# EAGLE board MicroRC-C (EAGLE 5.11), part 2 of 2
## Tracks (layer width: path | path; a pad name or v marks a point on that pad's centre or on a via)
+2V5  (via drill 0.41)
  Top 0.254: U10.1 U10.2 121.28,5.4 120.97,5.71 v120.97,6.67 | R46.2 R62.2 R16.2 v111.44,13.65
  Bottom 0.254: v120.97,6.67 118.11,6.67 117.79,6.98 117.79,8.89 117.47,9.21 112.08,9.21 111.44,9.84 v111.44,13.65
+3V3  (via drill 0.41, 0.61)
  Top 0.254: 108.58,51.59 TP2.TP
  Top 0.406: 121.21,46.6 120.97,46.6 v120.97,45.08
  Top 0.61: 121.21,46.6 U4.1 | v108.58,49.85 108.58,51.59
  Top 0.813: C21.+
  Top 1.016: v108.58,49.85 C21.+ v113.35,49.85
  SUPPLY 0.61: v120.97,45.08 120.97,49.21 120.33,49.85 v113.35,49.85 112.39,49.85 111.76,49.21 111.76,30.64 112.71,29.69 v117.47,29.69 | v108.58,49.85 108.58,46.67 109.54,45.72 109.54,34.61 107.63,32.7 v107.63,30.8
  pour Top (isolate 0.406, no thermals): 115.57,30.16 116.2,30.8 117.47,30.8 118.43,31.75 118.43,34.61 119.06,34.61 119.06,32.07 119.38,31.75 120.65,31.75 120.97,31.43 120.97,29.21 115.57,29.21
  pour Top (isolate 0.305, no thermals): 107,34.61 107.63,34.61 107.63,32.07 107.95,31.75 109.22,31.75 109.54,31.43 109.54,29.21 104.14,29.21 104.14,30.96 106.68,30.96 107,31.27
+5V  (via drill 0.41, 0.61)
  Top 0.178: R69.2 111.6,27.62 111.44,27.78 R70.2 110.49,27.62 110.33,27.78 v110.33,30.8 | R18.2 v62.23,44.77 | C11.1 v32.7,13.97 | U3.22 v28.26,11.11
  Top 0.254: R11.2 | R11.2 | R11.2 v50.48,51.12 | R10.2 v50.48,53.02 | C74.+ 81.92,30.16 v81.92,32.07 81.92,33.34 81.6,33.65 80.64,33.65 U6.18 | v77.47,26.35 C73.1 C30.2 TP1.TP | R20.2 v61.28,11.11 | C9.1 v46.04,54.93 U1.8 | R74.2 v133.67,4.13 | R79.2 40.64,40.96 40.01,41.59 v39.05,41.59 | U3.26 27.87,13.72 28.26,13.33 v28.26,11.11 | RN1.5 RN1.6 RN1.7 RN1.8 v43.02,11.43 | U8.24 98.51,34.68 99.06,34.13 v99.06,31.27 C72.1
  Top 0.406: R50.1 v66.04,32.38 | v28.26,11.11 C22.1
  Top 0.61: v20.8,33.65 R7.1
  Top 0.813: R6.1 v39.05,41.59
  Top 1.27: L3.2 v71.44,16.83
  other vias: 87.63,57.47 89.53,59.05 87.63,59.05 89.53,57.47
  pour SUPPLY (isolate 0.305, rank 2, no thermals): 0.95,75.88 0.95,52.7 5.71,52.7 6.03,52.39 6.03,49.85 5.71,49.53 0.95,49.53 0.95,0.95 133.99,0.95 133.99,4.13 arc90 133.67,4.44 arc90 133.35,4.13 133.35,2.86 arc-90 132.08,1.59 76.2,1.59 arc-90 74.93,2.86 74.93,23.81 arc-90 76.2,25.08 102.87,25.08 arc90 103.5,25.72 103.5,26.99 arc-90 104.78,28.26 121.92,28.26 arc90 122.56,28.89 122.56,33.02 arc-90 123.83,34.29 124.78,34.29 arc90 125.41,34.92 arc90 124.78,35.56 123.83,35.56 arc-90 122.56,36.83 122.56,71.12 arc90 121.92,71.75 53.34,71.75 arc90 52.7,71.12 52.7,59.69 arc-90 51.44,58.42 48.26,58.42 arc-90 46.99,59.69 46.99,75.88
  pour Top (isolate 0.61, rank 2, no thermals): 66.67,65.09 66.67,61.59 67.94,60.32 95.25,60.32 95.25,56.51 75.56,56.51 75.56,57.78 68.26,57.78 68.26,56.83 62.87,56.83 62.87,65.09
+12V  (via drill 0.41, 0.61)
  Top 0.254: v111.44,7.3 R73.2 | 119.38,23.81 v118.11,23.81 U7.8 | 119.38,23.81 | 119.38,23.81 C77.1
  Top 0.406: v120.97,7.94 U10.4 124.46,7.94 125.09,7.3 C75.1 | v95.57,13.65 C76.1 93.98,13.65 93.98,12.38 93.03,11.43 93.03,8.57 93.66,7.94 U5.4 | U4.3 121.28,49.6 121.28,51.75 121.76,52.23 v123.83,52.23
  other vias: 50.01,63.18 50.01,61.59 50.01,60.01
  pour Top (isolate 0.61, rank 5, no thermals): 27.3,61.59 27.3,57.78 59.05,57.78 59.69,57.15 59.69,54.61 60.96,54.61 60.96,67.94 61.59,68.58 66.36,68.58 66.36,69.85 60.01,69.85 58.74,68.58 58.74,64.77 58.1,64.13 41.91,64.13 41.27,64.77 41.27,69.85 40.32,70.8 36.2,70.8 36.2,69.85 39.05,69.85 39.37,69.53 39.37,62.23 38.73,61.59
  pour SUPPLY (isolate 0.305, rank 3, no thermals): 47.62,75.88 47.62,59.69 arc90 48.26,59.05 51.44,59.05 arc90 52.07,59.69 52.07,71.12 arc-90 53.34,72.39 121.92,72.39 arc-90 123.19,71.12 123.19,36.83 arc90 123.83,36.19 124.78,36.19 arc-90 126.05,34.92 arc-90 124.78,33.65 123.83,33.65 arc90 123.19,33.02 123.19,28.89 arc-90 121.92,27.62 104.78,27.62 arc90 104.14,26.99 104.14,25.72 arc-90 102.87,24.45 76.2,24.45 arc90 75.56,23.81 75.56,2.86 arc90 76.2,2.22 132.08,2.22 arc90 132.72,2.86 132.72,4.13 arc-90 133.67,5.08 arc-90 134.62,4.13 134.62,0.95 153.35,0.95 153.35,75.88
AGND  (via drill 0.41, 0.61)
  Top 0.178: 37.31,22.07 U12.2 | v34.61,26.99
  Top 0.254: C57.2 v84.14,27.62 | R77.1 v111.44,4.13 C65.2 | U7.4 v109.22,20 | C66.2 v138.11,4.13 | R78.1 v124.78,4.13 | C77.2 v122.87,23.49 | C76.2 92.71,13.33 | U5.11 92.39,7.94 92.87,7.46 v92.87,6.67 | C8.2 v34.61,26.99 | R33.1 v107,16.83 | R38.2 v79.69,10.48 | C38.1 v88.58,7.3 | R39.2 v84.14,10.48 | R40.2 v79.69,4.13 | D10.A v87.63,20.48 87.63,16.83 R37.2 | C19.2 v70.8,11.11 | C19.2 C19.2 arc-270 C19.2 | C19.2 68.9,13.65 R22.1 | R66.1 140.52,25.53 141.29,24.76 141.29,23.49 141.6,23.18 C60.2 R67.2 | C78.- v80.64,20.48 | R71.1 149.19,4.13 C62.2
  Top 0.406: C56.- v83.82,51.43 | U9.23 v113.67,31.75 | C63.1 v102.23,26.35 | v115.89,7.94 U10.11 | v91.12,13.65 C76.2 | C75.2 v129.22,7.3 | C55.- v87.63,51.43 | R23.1 C20.2 v61.91,54.93 | D7.A v58.42,55.88
  Top 0.61: C4.1 v34.61,24.92 34.61,22.54 | v42.86,56.83 52.39,56.83 53.34,55.88 D7.A | 34.61,22.54 C79.- | 37.31,22.07 34.61,22.07 34.61,22.54 | C79.- 34.61,22.54 | C79.-
  Bottom 0.406: v61.91,54.93 60.96,54.93 60.01,55.88 v58.42,55.88
  other vias: 106.68,44.77 117.47,26.67 140.97,49.85 140.97,37.46 134.94,28.57 128.27,20.32 129.86,31.11 152.4,31.75 152.4,2.54 99.38,69.21 99.38,67.94 70.8,6.67 70.8,2.22 109.22,25.72
  pour GROUND (isolate 0.305, rank 3, no thermals): 81.28,60.64 81.28,48.26 arc90 81.92,47.62 104.14,47.62 arc-90 105.41,46.35 105.41,44.45 arc90 106.05,43.81 112.08,43.81 arc90 112.71,44.45 112.71,46.51 arc-90 113.98,47.78 121.6,47.78 arc-90 122.87,46.51 122.87,34.29 arc90 123.51,33.65 124.78,33.65 arc-90 126.05,32.38 126.05,32.38 arc-90 124.78,31.11 123.51,31.11 arc90 122.87,30.48 122.87,28.89 arc-90 121.6,27.62 115.57,27.62 arc-90 114.3,28.89 114.3,31.59 arc90 113.67,32.23 arc90 113.03,31.59 113.03,28.1 arc-90 111.76,26.83 102.23,26.83 arc90 101.6,26.19 101.6,25.72 arc-90 100.33,24.45 86.04,24.45 arc-90 84.77,25.72 84.77,27.62 arc180 83.5,27.62 83.5,25.72 arc-90 82.23,24.45 76.36,24.45 arc90 75.72,23.81 75.72,13.02 arc-90 74.45,11.75 70.48,11.75 arc90 69.85,11.11 69.85,0.95 153.35,0.95 153.35,75.88 93.03,75.88 93.03,62.55 arc-90 91.76,61.28 81.92,61.28 arc90 81.28,60.64
  pour Top (isolate 0.61, rank 3, no thermals): 121.28,50.8 121.28,38.42 122.56,37.15 122.56,18.1 138.11,18.1 138.11,28.42 142.24,28.42 142.24,50.8 141.6,51.43 140.34,51.43 139.7,52.07 139.7,59.69 140.34,60.32 144.15,60.32 147,57.47 147,49.21 152.08,49.21 152.72,48.58 152.72,32.7 151.76,32.07 151.76,31.43 152.72,30.48 152.72,4.13 150.81,2.22 74.93,2.22 73.98,3.17 73.98,13.97 72.71,13.97 72.39,14.29 72.39,15.24 70.17,15.24 70.17,1.59 153.35,1.59 153.35,75.25 144.3,75.25 144.3,61.91 143.99,61.59 133.67,61.59 133.35,61.28 133.35,50.8
  pour Bottom (isolate 0.61, rank 2, no thermals): 34.92,75.25 34.92,28.26 33.97,27.3 33.97,23.34 34.29,23.02 38.42,23.02 38.42,35.24 42.23,35.24 42.23,54.61 44.77,57.15 49.53,57.15 58.42,66.04 116.84,66.04 120.65,62.23 120.65,51.12 128.27,51.12 128.27,36.19 127.95,35.88 126.68,35.88 126.36,35.56 126.36,34.29 126.68,33.97 127.95,33.97 128.27,33.65 128.27,28.26 126.36,28.26 126.36,25.08 123.19,25.08 122.24,24.13 122.24,19.37 129.54,19.37 130.49,18.41 136.21,18.41 136.21,16.19 142.88,16.19 142.88,8.25 139.06,8.25 139.06,7.3 129.86,7.3 129.54,7.62 128.91,7.62 128.59,7.3 122.56,7.3 120.02,4.76 110.49,4.76 109.54,5.71 105.41,5.71 102.87,3.17 80.96,3.17 78.11,6.03 78.11,8.57 70.17,8.57 70.17,1.59 153.35,1.59 153.35,75.25
  pour Top (isolate 0.61, no thermals): 104.78,47.31 107.31,47.31 107.63,46.99 107.63,42.23 105.73,42.23 105.73,44.77 105.41,45.08 105.09,45.08 104.78,45.4
  pour Top (isolate 0.406, rank 2, no thermals): 115.25,27.94 120.97,27.94 120.97,25.72 113.35,25.72 112.71,25.08 107,25.08 107,25.4 107.95,26.35 114.94,26.35 115.25,26.67
  pour Top (no thermals): 97.47,69.21 98.11,69.85 100.01,69.85 100.01,67.31 98.11,67.31 97.47,67.94
AUX_AUDIO  (via drill 0.41)
  Top 0.254: X3.8 142.88,53.34 142.88,43.81 | v142.88,21.59 v142.88,36.19 142.88,43.81 | C45.2 v124.78,13.65 | 142.88,43.81 R49.2
  Bottom 0.254: v142.88,21.59 142.88,15.87 142.24,15.24 127.32,15.24 125.73,13.65 v124.78,13.65 | J2.3 130.81,29.84 137.16,36.19 v142.88,36.19
  Bottom 0.61: X3.8 X4.8
AUX_AUDIO_OUT  (via drill 0.41)
  Top 0.254: U7.1 v109.22,23.81 TP4.TP | U8.22 94.35,33.28 94.93,32.7 v94.93,31.75
  Bottom 0.254: v94.93,31.75 94.93,24.76 95.89,23.81 v109.22,23.81
AVR_5V  (via drill 0.41, 0.61)
  Top 0.178: D1.C C1.1 | U2.52 40.11,31.22 39.85,30.96 C2.1
  Top 0.254: R5.2 C1.1 60.96,18.41 60.64,18.73 60.64,20.95 | 57.01,24.84 U2.21 | U2.52 42.34,31.22 v43.02,31.91
  Top 0.406: R5.2 59.05,16.83 | v55.56,24.84 57.01,24.84
  Top 0.813: L2.2 60.64,20.95 v60.64,22.7
  SUPPLY 0.406: v60.64,22.7 56.2,22.7 55.56,23.34 v55.56,24.84 53.42,24.84 46.35,31.91 v43.02,31.91
AVR_REF
  Top 0.178: 39.21,21.75 U12.1
  Top 0.254: C4.2 37.78,23.49 38.1,23.18 38.89,23.18 39.21,22.86 39.21,21.75 | U2.64 41.41,21.75 39.21,21.75 | 39.21,21.75 | 39.21,21.75 U12.1
B_CTS
  Top 0.178: U3.6 19.34,11.77 19.05,12.06 7.62,12.06 6.67,13.02 6.67,17.46 6.87,17.67 X2.8
B_DCD
  Top 0.178: X2.1 12.72,24.59 13.49,23.81 13.49,20.32 13.81,20 21.59,20 22.86,18.73 22.86,11.27 22.06,10.47 U3.8
B_DSR
  Top 0.178: X2.6 12.36,23.2 13.02,22.54 13.02,20.16 13.65,19.53 21.43,19.53 22.38,18.57 22.38,11.75 21.76,11.12 U3.7
B_DTR  (via drill 0.41)
  Top 0.178: U3.10 18.29,9.17 18.1,9.37 v18.1,10.64
  Bottom 0.178: X2.4 17.53,16.28 18.1,15.72 v18.1,10.64
B_RI
  Top 0.178: U3.4 19.58,13.07 19.05,12.54 12.7,12.54 12.38,12.86 12.38,14.6 12.09,14.9 X2.9
B_RTS
  Top 0.178: X2.7 6.46,20.43 5.71,19.68 5.71,12.7 7.3,11.11 16.83,11.11 17.14,10.79 17.14,8.89 17.52,8.52 U3.11
B_RXD
  Top 0.178: X2.2 12.15,21.82 12.54,21.43 12.54,20 13.49,19.05 21.27,19.05 21.91,18.41 21.91,12.7 21.63,12.42 U3.5
B_TXD
  Top 0.178: X2.3 6.67,19.05 6.19,18.57 6.19,12.86 7.46,11.59 18.73,11.59 19.05,11.27 19.05,10.16 19.39,9.82 U3.9
BEEP_PWM  (via drill 0.41)
  Top 0.178: R68.1 v73.66,16.83 TP7.TP | U2.15 54.41,18.93 55.24,18.1 v55.24,17.3
  Bottom 0.178: v55.24,17.3 66.99,17.3 68.26,18.57 73.34,18.57 73.66,18.26 v73.66,16.83
CGND  (via drill 0.61)
  Top 0.178: R13.2 111.12,53.97 110.81,54.29
  Bottom 0.61: X3.4 X4.4
  other vias: 94.3,69.21 94.3,67.94
  pour Top (isolate 0.61, rank 6, no thermals): 12.7,75.25 12.7,70.48 15.56,70.48 15.88,70.17 15.88,64.77 17.14,64.77 17.78,65.41 17.78,72.39 18.41,73.02 30.8,73.02 31.43,72.39 31.43,69.85 33.66,69.85 33.97,69.53 33.97,66.04 34.29,65.72 35.56,65.72 35.88,65.41 35.88,62.86 37.78,62.86 37.78,68.58 37.47,68.9 35.88,68.9 35.56,69.21 35.56,71.75 35.88,72.07 40.96,72.07 42.23,70.8 58.74,70.8 59.37,71.44 69.22,71.44 69.85,70.8 69.85,61.91 70.48,61.28 95.89,61.28 96.52,60.64 96.52,56.51 110.17,56.51 110.17,53.66 111.44,53.66 111.44,56.51 122.56,56.51 122.56,53.66 124.14,53.66 124.78,53.02 124.78,51.43 132.08,51.43 132.08,61.91 133.03,62.86 143.19,62.86 143.19,64.13 129.86,64.13 126.36,60.64 101.92,60.64 101.92,75.25
COM_CTS  (via drill 0.41)
  Top 0.178: U3.17 24.2,7.87 v23.5,8.57 | U2.14 53.61,17.89 53.34,17.62 v52.55,17.62
  Bottom 0.178: v23.5,8.57 23.5,15.87 23.97,16.35 47.15,16.35 49.05,18.26 50.64,18.26 51.28,17.62 v52.55,17.62
COM_DCD  (via drill 0.41)
  Top 0.178: U2.8 48.81,18.18 v49.53,17.46 | v27.78,9.37 27.78,6.98 27.37,6.57 U3.15
  Bottom 0.178: v49.53,17.46 49.53,16.51 50.16,15.87 50.16,14.29 49.85,13.97 47.62,13.97 46.67,14.92 27.3,14.92 26.99,14.6 26.99,10.95 27.78,10.16 v27.78,9.37
COM_DSR  (via drill 0.41)
  Top 0.178: U3.16 23.74,7.22 23.02,7.94 v22.23,7.94 | U2.17 56.67,21.62 56.67,19.21 56.04,18.57 56.04,16.51 55.72,16.19 v53.02,16.19
  Bottom 0.178: v53.02,16.19 53.5,16.67 53.5,18.57 53.18,18.89 48.74,18.89 46.83,16.99 22.86,16.99 22.23,16.35 v22.23,7.94
COM_DTR  (via drill 0.41)
  Top 0.178: U2.35 53.61,40.91 v55.24,42.54 | v61.28,33.97 62.23,33.97 62.87,34.61 67.63,34.61 68.42,33.81 v69.22,33.81 | 20.64,7.22 22.94,7.22 23.65,6.51 v23.65,5.71 | U3.12 20.64,7.87 20.64,7.22 | 20.64,7.22 U3.13
  Bottom 0.178: v69.22,33.81 69.22,36.19 69.85,36.83 82.55,36.83 83.19,36.19 83.19,25.72 82.55,25.08 78.11,25.08 77.47,24.45 77.47,10.48 76.83,9.84 59.37,9.84 56.83,12.38 30,12.38 29.69,12.06 29.69,9.05 26.35,5.71 v23.65,5.71 | v55.24,42.54 57.63,42.54 58.42,41.75 60.64,41.75 61.28,41.12 61.28,34.13 v61.28,33.97
COM_RXD  (via drill 0.41)
  Top 0.178: R3.2 v49.21,14.92 49.21,15.56 48.9,15.87 44.77,15.87 44.01,16.63 U2.2 | v24.77,8.89 25.4,8.89 25.77,8.52 U3.18
  Bottom 0.178: v49.21,14.92 47.94,14.92 47.15,15.72 26.35,15.72 26.04,15.4 26.04,9.21 25.72,8.89 v24.77,8.89
COM_TXD  (via drill 0.41)
  Top 0.178: R1.2 51.75,14.6 50.8,15.56 v50.8,16.51 45.24,16.51 44.81,16.94 U2.3 | U3.14 22,6.57 22.23,6.35 v22.23,5.71
  Bottom 0.178: v50.8,16.51 50.8,13.81 50.01,13.02 29.69,13.02 29.05,12.38 29.05,9.21 26.83,6.98 22.54,6.98 22.23,6.67 v22.23,5.71
COS  (via drill 0.41)
  Top 0.178: v120.97,55.56 120.97,53.66 119.38,52.07 R13.1 v110.81,52.07 | R19.2 v66.67,51.43
  Bottom 0.178: v120.97,55.56 120.97,65.41 121.6,66.04 X3.3 | v110.81,52.07 102.87,52.07 100.97,53.97 66.99,53.97 66.67,53.66 v66.67,51.43
  Bottom 0.61: X3.3 X4.3
CS_DTMF  (via drill 0.41)
  Top 0.178: U2.38 51.21,34.38 50.8,33.97 48.26,33.97 47.62,33.34 v47.62,23.97 | v70.48,31.75 U6.10
  Bottom 0.178: v47.62,23.97 52.39,23.97 56.67,19.68 61.91,19.68 63.66,21.43 67.15,21.43 68.58,22.86 68.58,28.26 70.48,30.16 v70.48,31.75
DISC_AUDIO
  Top 0.254: X3.6 144.46,58.42 146.05,56.83 146.05,49.21 146.72,48.54 R26.3 151.81,48.54 152.08,48.26 152.08,33.65 151.72,33.3 R27.3
  Bottom 0.61: X3.6 X4.6
DTMF_Q1
  Top 0.178: 61.12,35.08 59.85,33.81 59.85,31.75 59.32,31.22 U2.29 | 61.12,35.08 | 61.12,35.08 71.6,35.08 71.75,34.92 U6.11
DTMF_Q2
  Top 0.178: U6.12 73.03,34.92 72.39,35.56 60.96,35.56 59.37,33.97 59.37,32.54 58.85,32.02 U2.30
DTMF_Q3
  Top 0.178: U6.13 74.3,34.92 73.18,36.04 60.8,36.04 58.9,34.13 58.9,33.34 58.38,32.82 U2.31
DTMF_Q4
  Top 0.178: U6.14 75.56,34.92 73.98,36.51 60.64,36.51 58.42,34.29 58.42,33.97 58.07,33.62 U2.32
EXP_IO0  (via drill 0.41)
  Top 0.178: v44.77,45.4 v53.98,45.4 | U2.4 45.61,24.55 45.09,25.08 v45.09,27.62
  Bottom 0.178: v53.98,45.4 53.98,55.88 60.33,62.23 114.94,62.23 116.84,60.32 116.84,47.31 120.33,43.81 126.05,43.81 J2.15 | v45.09,27.62 45.09,33.34 44.13,34.29 44.13,43.81 44.77,44.45 v44.77,45.4
EXP_IO1  (via drill 0.41)
  Top 0.178: v45.72,46.35 v50.16,46.35 | U2.5 46.41,24.71 46.04,25.08 v46.04,26.67
  Bottom 0.178: J2.19 127.16,50.16 125.89,48.89 120.33,48.89 119.38,49.85 119.38,61.59 116.2,64.77 59.05,64.77 51.59,57.31 | 51.59,57.31 | 51.59,57.31 51.44,57.15 51.44,48.42 50.16,47.15 v50.16,46.35 | v46.04,26.67 46.04,33.34 44.77,34.61 44.77,43.5 45.72,44.45 v45.72,46.35
EXP_IO2  (via drill 0.41)
  Top 0.178: U2.37 52.07,35.42 v52.07,43.18
  Bottom 0.178: v52.07,43.18 52.07,46.99 52.7,47.62 52.7,56.51 59.69,63.5 115.57,63.5 118.11,60.96 118.11,48.58 119.86,46.83 122.71,46.83 123.19,46.35 126.05,46.35 J2.17
EXT_COS  (via drill 0.41)
  Top 0.178: Q5.3 65.09,41.27 R18.1 62.23,40.96 v59.37,40.96 | U2.34 54.41,40.44 v55.24,41.27
  Bottom 0.178: v59.37,40.96 57.78,40.96 57.47,41.27 v55.24,41.27
FAN
  Bottom 0.61: X3.2 X4.2
  pour Top (isolate 0.61, rank 2, no thermals): 143.19,69.21 140.97,69.21 139.7,70.48 139.7,71.75 139.38,72.07 115.25,72.07 114.94,71.75 114.94,60.96 125.73,60.96 130.18,65.41 139.38,65.41 139.7,65.72 139.7,66.67 140.97,67.94 143.19,67.94
FAN_DRIVE  (via drill 0.41)
  Top 0.178: v63.5,46.35 R17.1 | U2.39 50.41,36.26 50.16,36.51 v50.16,37.46
  Bottom 0.178: v63.5,46.35 61.91,46.35 60.96,47.31 55.56,47.31 55.24,46.99 55.24,44.77 54.93,44.45 53.34,44.45 53.02,44.13 53.02,42.23 52.7,41.91 51.75,41.91 50.16,40.32 v50.16,37.46
GND  (via drill 0.41, 0.61)
  Top 0.178: C5.2 59.53,11.11 v59.53,12.7 | C12.1 v14.92,13.97 | U3.23 25.42,11.77 v24.77,11.11
  Top 0.254: U1.4 v40.8,51.12 | C9.2 v50.48,54.93 | 70.48,42.86 U6.9 | 75.56,42.86 U6.5 | U6.6 74.3,42.86 | U9.26 v117.47,35.24 | U2.22 58.2,25.62 v58.74,25.08 | U2.53 42.6,30.42 v43.18,29.84 | U2.63 42.35,22.42 v42.86,21.91 | C7.2 64.77,29.21 v66.67,29.21 | v66.67,24.45 64.77,24.45 C6.2 | v100.49,27.78 | C72.2 99.06,27.78 v100.49,27.78 | Q5.2 64.2,43.33 v64.2,45.08 | U3.25 25.66,13.07 v25.08,13.65 | D2.A 69.37,41.27 69.53,41.43 v69.53,42.86 | U8.12 88.5,41.59 v87.31,41.59
  Top 0.406: C2.2 v33.5,30.96 | v69.53,42.86 70.48,42.86 | 74.3,42.86 75.56,42.86 | U6.5 v75.56,44.45 | v116.2,40.96 U9.4 | U9.26 v117.47,31.75 | v79.06,26.67 81.28,26.67 C74.- | C22.2 v32.7,11.11 | C53.2 v91.12,47.31 | C54.2 v101.28,47.31 | C73.2 v79.06,29.53 | Q1.2
  Top 0.61: v62.87,15.24 C1.2 | Q2.3 42.95,48.49 41.91,49.53 v38.73,49.53 | v20.32,30.64 Q1.2
  Top 0.813: U4.4 118.43,48.1 | 118.43,48.1 U4.2 | 118.43,48.1
  Top 1.27: C3.- v71.12,20.95
  Bottom 0.254: J2.6 121.6,32.38 118.75,35.24 v117.47,35.24
  other vias: 107.63,27.46 69.61,52.39 74.22,52.39 113.98,46.67 113.98,45.4 32.46,52.39 32.46,56.2 89.22,69.21 89.22,67.94 2.22,74.29
  pour GROUND (isolate 0.305, rank 2, no thermals): 0.95,75.88 0.95,52.7 5.71,52.7 6.03,52.39 6.03,49.85 5.71,49.53 0.95,49.53 0.95,0.95 69.22,0.95 69.22,11.11 arc-90 70.48,12.38 74.45,12.38 arc90 75.09,13.02 75.09,23.81 arc-90 76.36,25.08 82.23,25.08 arc90 82.87,25.72 82.87,27.62 arc-180 85.41,27.62 85.41,25.72 arc90 86.04,25.08 100.33,25.08 arc90 100.97,25.72 100.97,26.19 arc-90 102.23,27.46 111.76,27.46 arc90 112.39,28.1 112.39,31.75 arc-90 113.67,32.86 113.67,32.86 arc-90 114.94,31.59 114.94,28.89 arc90 115.57,28.26 121.6,28.26 arc90 122.24,28.89 122.24,30.48 arc-90 123.51,31.75 124.78,31.75 arc90 125.41,32.38 arc90 124.78,33.02 123.51,33.02 arc-90 122.24,34.29 122.24,46.51 arc90 121.6,47.15 113.98,47.15 arc90 113.35,46.2 113.35,44.45 arc-90 112.08,43.18 106.05,43.18 arc-90 104.78,44.45 104.78,46.35 arc90 104.14,46.99 81.92,46.99 arc-90 80.64,48.26 80.64,60.64 arc-90 81.92,61.91 91.76,61.91 arc90 92.39,62.55 92.39,75.88
  pour Top (isolate 0.406, no thermals): 62.55,25.4 62.55,28.26 66.04,28.26 66.04,30.32 70.64,30.32 70.64,23.34 66.04,23.34 66.04,25.4
  pour Top (isolate 0.406, no thermals): 28.26,56.67 28.26,51.91 34.92,51.91 34.92,56.67
  pour Top (isolate 0.406, no thermals): 69.06,46.99 74.77,46.99 74.77,57.15 69.06,57.15
  pour Top (isolate 0.61, no thermals): 120.17,44.77 109.22,44.77 109.22,47.62 114.3,47.62 114.62,47.94 114.62,50.16 114.94,50.48 120.17,50.48 120.17,48.58 121.76,48.58 121.76,47.62 120.17,47.62
  pour Bottom (isolate 0.61, rank 6, no thermals): 0.64,75.25 34.29,75.25 34.29,28.57 33.34,27.62 33.34,23.02 33.97,22.38 43.18,22.38 43.18,20.16 41.12,18.1 21.91,18.1 20.95,17.14 20.95,5.4 21.91,4.44 31.11,4.44 31.43,4.76 31.43,5.71 31.75,6.03 32.7,6.03 33.02,5.71 33.02,4.76 33.34,4.44 37.47,4.44 37.78,4.76 37.78,6.35 42.23,6.35 42.23,4.76 42.55,4.44 52.7,4.44 52.7,6.98 52.39,7.3 51.44,7.3 51.12,7.62 51.12,8.25 51.44,8.57 57.78,8.57 58.1,8.25 58.1,7.62 57.78,7.3 56.83,7.3 56.52,6.98 56.52,4.44 68.58,4.44 68.58,6.98 68.26,7.3 67.31,7.3 66.99,7.62 66.99,8.25 67.31,8.57 69.37,8.57 69.37,1.59 0.64,1.59 0.64,49.53 5.71,49.53 6.03,49.85 6.03,52.39 5.71,52.7 0.64,52.7
  pour Bottom (no thermals): 9.84,72.39 9.84,69.21 3.81,69.21 3.81,59.69 0.95,59.69 0.95,72.39
  pour Top (isolate 0.305, no thermals): 104.14,25.88 104.14,27.94 109.86,27.94 109.86,27.15 107.79,27.15 106.52,25.88
  pour Top (no thermals): 88.58,67.31 88.58,69.85 90.49,69.85 91.12,69.21 91.12,67.94 90.49,67.31
  pour Top (isolate 0.61, rank 6, no thermals): 0.95,75.25 0.95,1.59 69.22,1.59 69.22,8.89 66.67,8.89 66.67,6.98 67.63,6.98 67.94,6.67 67.94,2.86 67.31,2.22 44.45,2.22 42.55,4.13 42.55,6.35 37.78,6.35 37.78,3.49 37.47,3.17 33.34,3.17 33.02,3.49 33.02,6.03 31.43,6.03 31.43,4.13 30.8,3.49 14.61,3.49 13.97,4.13 13.97,10.16 6.99,10.16 5.71,11.43 5.71,20.95 6.67,20.95 6.67,23.81 7.62,24.76 9.53,24.76 10.48,25.72 13.65,25.72 13.65,40.64 12.22,40.64 11.11,41.75 11.11,58.74 3.49,58.74 2.86,59.37 2.86,68.26 3.49,68.9 11.75,68.9 11.75,75.25
I2C_SCL  (via drill 0.41)
  Top 0.178: R10.1 47.31,52.7 46.99,52.39 v46.04,52.39 U1.6 | U2.25 57.01,27.94 v54.93,27.94 | v49.37,49.53 50.48,49.53 51.12,50.16 v54.93,50.16
  Bottom 0.178: v54.93,27.94 48.26,27.94 47.62,28.57 47.62,40.32 46.51,41.43 46.51,48.74 46.04,49.21 v46.04,52.39 48.9,52.39 49.37,51.91 v49.37,49.53 | J2.13 126.05,41.27 123.19,41.27 122.56,41.91 117.47,41.91 116.2,43.18 116.2,60.01 114.62,61.59 60.64,61.59 54.93,55.88 v54.93,50.16
I2C_SDA  (via drill 0.41)
  Top 0.178: 47.15,51.12 v47.15,49.53 47.15,48.89 47.31,48.74 50.8,48.74 51.28,49.21 v55.72,49.21 | U2.26 57.01,28.89 v55.56,28.89
  Top 0.254: U1.5 47.15,51.12 R11.1
  Bottom 0.178: v55.56,28.89 48.58,28.89 48.26,29.21 48.26,40.64 47.15,41.75 v47.15,49.53 | J2.11 126.05,38.73 123.19,38.73 121.92,40 118.43,40 115.57,42.86 115.57,59.69 114.3,60.96 60.96,60.96 55.72,55.72 v55.72,49.21
INT_DTMF  (via drill 0.41)
  Top 0.178: v76.83,35.4 U6.15 | U2.6 47.23,19.82 v47.23,22.22
  Bottom 0.178: v47.23,22.22 53.18,22.22 56.36,19.05 62.23,19.05 63.98,20.8 67.47,20.8 69.22,22.54 69.22,27.94 71.75,30.48 71.75,34.45 72.71,35.4 v76.83,35.4
INT_EXP  (via drill 0.41)
  Top 0.178: v49.21,40.32 47.94,40.32 47.31,40.96 R79.1 | U2.27 56.1,29.62 55.88,29.84 v54.93,29.84
  Bottom 0.178: J2.18 120.33,47.62 118.75,49.21 118.75,61.28 115.89,64.13 59.37,64.13 52.07,56.83 52.07,47.94 51.12,46.99 51.12,42.23 v49.21,40.32 49.21,30.16 49.53,29.84 v54.93,29.84
INT_ISD  (via drill 0.41)
  Top 0.178: v81.92,35.4 81.92,36.19 arc0 82.23,36.51 100.33,36.51 100.97,37.15 115.89,37.15 116.2,36.83 U9.25 | R69.1 113.67,30.32 113.82,30.48 114.62,30.48 116.2,32.07 U9.25 | U2.7 48.02,19.82 v48.02,21.11
  Top 0.254: U9.25
  Bottom 0.178: v81.92,35.4 78.74,35.4 77.63,34.29 73.03,34.29 72.39,33.65 72.39,30.16 69.85,27.62 69.85,22.22 67.79,20.16 64.29,20.16 62.55,18.41 56.04,18.41 53.34,21.11 v48.02,21.11
INT_MX828  (via drill 0.41)
  Top 0.178: v81.6,40.96 82.55,40.96 83.19,40.32 91.6,40.32 91.75,40.47 U8.7 | v67.63,32.38 67.63,33.65 67.31,33.97 63.18,33.97 62.87,33.65 R50.2 61.59,32.38 59.63,30.42 U2.28
  Bottom 0.178: v81.6,40.96 68.58,40.96 67.63,40 v67.63,32.38
INT_RAC  (via drill 0.41)
  Top 0.178: v114.94,36.19 U9.24 114.94,31.75 114.14,30.96 111.76,30.96 111.44,30.64 R70.1 | U2.9 49.61,20.71 48.42,21.91 v48.42,26.35
  Bottom 0.178: v114.94,36.19 114.94,59.37 113.98,60.32 61.28,60.32 56.52,55.56 56.52,50.32 57.31,49.53 64.14,49.53 65.09,48.58 65.09,43.5 62.87,41.27 62.87,33.02 62.23,32.38 59.37,32.38 58.74,31.75 58.74,26.99 58.1,26.35 v48.42,26.35
LCD_BKLITE  (via drill 0.41)
  Top 0.178: v45.72,43.18 R9.1 | v45.72,43.18 | U2.1 43.21,18.76 43.02,18.57 v43.02,17.78
  Bottom 0.178: v45.72,43.18 45.72,41.27 46.99,40 46.99,26.03 46.67,25.72 43.02,25.72 42.7,25.4 42.7,23.81 44.13,22.38 44.13,18.1 43.81,17.78 v43.02,17.78
LCD_E
  Top 0.178: J1.6 21.59,36.19 20.64,37.15 20.64,50.16 21.27,50.8 29.69,50.8 30.64,49.85 30.64,39.21 30.96,38.89 46.51,38.89 48.81,36.59 U2.41
LCD_RS
  Top 0.178: J1.4 20.16,36.35 20.16,50.32 21.11,51.28 29.84,51.28 31.11,50.01 31.11,39.53 31.27,39.37 46.99,39.37 49.61,36.75 U2.40
LCD_RW
  Top 0.178: J1.5 24.13,37.46 21.75,37.46 21.11,38.1 21.11,50.01 21.43,50.32 29.53,50.32 30.16,49.69 30.16,39.05 30.8,38.42 46.04,38.42 48.01,36.44 U2.42
LED_PWR  (via drill 0.41)
  Top 0.178: v38.73,33.18 R8.1 | v41.75,35.24 43.02,33.97 46.99,33.97 47.21,34.19 U2.43
  Bottom 0.178: v41.75,35.24 39.37,35.24 38.73,34.61 v38.73,33.18
MIX_BUSS
  Top 0.254: R72.1 R76.2 R59.2 136.84,11.75 136.53,12.06 134.94,12.06 | 134.94,12.06 132.72,12.06 132.4,11.75 C51.1 | 134.94,12.06 R64.2 134.94,14.92 134.62,15.24 128.27,15.24 127.95,15.56 R51.2
MIX_INSERT  (via drill 0.41)
  Top 0.254: v121.6,19.68 C47.1 121.6,15.56 121.28,15.24 114.94,15.24 114.62,14.92 R16.1 | J2.4 126.05,28.57 v126.05,25.56
  Bottom 0.254: v126.05,25.56 122.71,25.56 121.6,24.45 v121.6,19.68
MUTE_AUX
  Top 0.178: U7.7 114.62,22.54 114.3,22.86 114.3,24.45 114.62,24.76 121.28,24.76 122.08,25.56 122.08,36.99 121.28,37.78 119.06,37.78 118.75,38.1 100.33,38.1 99.69,37.46 60.33,37.46 57.94,35.08 56.36,35.08 53.66,32.38 53.66,23.97 55.21,22.42 U2.18
MUTE_RX
  Top 0.178: U7.3 112.71,21.27 113.03,21.59 113.03,24.61 113.67,25.24 121.13,25.24 121.6,25.72 121.6,36.83 121.13,37.31 118.9,37.31 118.59,37.62 100.65,37.62 100.01,36.99 60.48,36.99 58.1,34.61 56.52,34.61 54.13,32.23 54.13,24.29 55.2,23.22 U2.19
N$1
  pour Top (isolate 0.61, no thermals): 4.13,67.31 4.45,67.63 11.43,67.63 12.7,66.36 12.7,64.77 4.45,64.77 4.13,65.09
N$2
  Top 0.254: C8.1 38.73,26.99 39.05,26.67 39.05,24.13 39.96,23.22 U2.62
  Top 0.406: C8.1
N$3
  Top 0.254: R82.2 C45.1
N$4  (via drill 0.41)
  Top 0.254: R26.2 146.69,46.04 146.05,45.4 146.05,39.69 144.78,38.42 v144.78,33.65 | C39.2 v107.31,20
  Bottom 0.254: v107.31,20 107.31,20.95 107.63,21.27 114.3,21.27 114.62,20.95 114.62,16.19 114.94,15.87 117.16,15.87 119.06,17.78 136.53,17.78 137.16,18.41 137.16,20.64 138.75,22.22 138.75,26.03 139.38,26.67 139.38,27.94 138.75,28.57 138.75,32.7 139.7,33.65 v144.78,33.65
N$5  (via drill 0.41)
  Top 0.254: v138.11,13.65 138.11,14.6 138.75,15.24 139.06,15.24 139.38,15.56 C58.1 | 114.62,20 R62.1 | v113.67,20 114.62,20 | U7.6 114.94,21.27 114.62,20.95 114.62,20
  Bottom 0.254: v138.11,13.65 137.16,12.7 113.98,12.7 113.67,13.02 v113.67,20
N$6
  Top 0.254: R64.1 136.84,14.92 137.16,15.24 137.48,15.24 138.11,15.87 138.11,18.1 138.43,18.41 143.83,18.41 144.78,19.37 144.78,31.75 145.73,32.7 145.73,37.94 146.21,38.42 R63.2
N$7
  Top 0.254: R65.2 136.84,20.16 136.84,20.32 138.02,21.49 R66.2
N$8
  Top 0.254: C63.2 102.23,31.43 102.55,31.75 104.46,31.75 104.78,32.07 U9.16
N$9
  Top 0.254: JP5.2 R12.2
N$10
  Top 0.254: U8.11 89.15,43.25 88.9,43.5 84.14,43.5 83.82,43.81 C56.+
N$11
  Top 0.254: R83.2 C52.1
N$12
  Top 0.254: R42.2 92.71,21.91 93.34,21.27 95.25,21.27 95.89,20.64 JP4.1
N$13
  pour Top (isolate 0.61, rank 3, no thermals): 18.73,46.67 16.51,46.67 16.51,48.89 17.46,49.85 17.46,56.83 19.05,58.42 19.05,71.12 20.64,71.12 20.64,62.86 21.91,61.59 26.35,61.59 26.35,56.2 21.91,56.2 20.95,55.24 20.95,50.16 18.73,47.94
N$14
  pour Top (isolate 0.61, no thermals): 12.7,63.5 12.7,61.91 10.79,60.01 4.45,60.01 4.13,60.32 4.13,63.18 4.45,63.5
N$15  (via drill 0.41)
  Top 0.254: C59.1 v133.67,16.83 R65.1 | v138.11,20 R67.1 C60.1
  Bottom 0.254: v133.67,16.83 136.84,16.83 138.11,18.1 v138.11,20 TP8.TP
N$16
  Top 0.178: U6.7 73.18,42.86
  Top 0.254: U6.7 | 73.18,42.86 Y2.2
N$17
  Top 0.178: Y2.1 | Y2.1
  Top 0.254: U6.8 71.75,44.13 Y2.1
N$18
  Top 0.178: U6.4 76.83,41.27 76.99,41.12 80.49,41.12 80.64,41.27 U6.1
N$19
  pour Top (isolate 0.61, rank 3, no thermals): 22.23,72.07 29.84,72.07 30.16,71.75 30.16,68.26 30.48,67.94 33.02,67.94 33.02,65.41 33.34,65.09 33.34,62.86 22.54,62.86 21.91,63.5 21.91,71.75
N$20
  Top 0.254: Y4.2 37.15,54.93 U1.1
N$21
  Top 0.254: Y4.1 37.15,53.66 U1.2
N$22
  Top 0.254: C61.1 R68.2
N$23
  Top 0.254: R76.1 144.15,10.48 146.05,12.38 147.48,12.38 149.86,14.76 149.86,16.35 148,18.22 R75.2
N$24
  Top 0.254: 114.62,5.71 115.57,5.71 115.89,6.03 115.89,6.35 116.2,6.67 U10.12 | 114.62,5.71 108.58,5.71 108.27,5.4 C65.1 | 114.62,5.71 R77.2 | 114.62,5.71 R73.1
N$25  (via drill 0.41)
  Top 0.254: C64.2 v120.33,16.83
  Bottom 0.254: v120.33,16.83 126.36,16.83 127.32,15.87 141.6,15.87 141.92,16.19 141.92,24.13 143.47,25.68 R75.3
N$26
  Top 0.254: U6.2 79.38,44.45 80.33,45.4 R45.2 79.06,46.67 78.74,46.99 78.74,48.58 | 78.74,48.58 78.74,51.91 78.42,52.23 77.15,52.23 C40.2 | R41.2 77.15,48.42 77.31,48.58 78.74,48.58
N$27  (via drill 0.41)
  Top 0.254: v89.53,26.35 C41.2
  Bottom 0.254: v89.53,26.35 90.49,26.35 90.81,26.03 JP4.3
N$28
  Top 0.254: U6.3 78.11,44.45 77.15,45.4 R41.1 76.83,46.99 76.04,46.99 75.72,47.31 75.72,50.16 76.04,50.48 C40.1
N$29
  Top 0.254: R32.2 73.5,27.62 73.66,27.78 73.66,29.37 arc0 73.82,29.53 C30.1 74.93,30.48 75.25,30.8 79.06,30.8 79.38,31.11 U6.17
N$30
  Top 0.254: 60.64,28.1 60.64,29.05 60.96,29.37 62.87,29.37 C7.1 | 60.64,28.1 Y1.1 | U2.24 59.77,27.22 60.64,28.1
N$31  (via drill 0.41)
  Top 0.254: v36.2,6.35 R14.2
  Bottom 0.178: JP5.4 41.27,9.52 40.96,9.84 36.51,9.84 36.2,9.52 v36.2,6.35
N$32
  Top 0.254: U6.16 78.11,31.91 77.79,31.59 72.71,31.59 72.39,31.27 R32.1
N$33  (via drill 0.41)
  Top 0.254: v106.05,31.75 U9.17 | C59.2 129.38,16.83 129.22,16.99 v129.22,18.73
  Bottom 0.254: v129.22,18.73 117.16,18.73 116.52,19.37 116.52,27.94 115.25,29.21 106.68,29.21 106.05,29.84 v106.05,31.75
N$34
  Top 0.178: U3.3 18.1,13.72 C12.2
N$35
  Top 0.254: C44.2 107.31,13.65 107,13.33 107,7.62 107.31,7.3 R48.1
N$36
  Top 0.178: U3.27 29.53,14.37 C11.2
N$37  (via drill 0.41)
  Top 0.254: v102.23,33.02 v102.23,36.19 | v115.89,16.83 C64.1
  Top 0.406: v104.78,40.96 U9.13
  Bottom 0.254: v102.23,33.02 102.23,27.62 103.19,26.67 114.94,26.67 115.89,25.72 v115.89,16.83 | v104.78,40.96 103.5,40.96 102.23,39.69 v102.23,36.19
N$38
  Top 0.254: C6.1 62.87,24.29 60.96,24.29 60.64,24.61 Y1.2 60.64,25.56 59.78,26.42 U2.23
N$39
  Top 0.178: U3.1 20.58,16.89 20.32,17.14 C13.1
N$40
  Top 0.254: R45.1 C43.2
N$41
  Top 0.254: U8.10 89.8,43.55 89.22,44.13 87.95,44.13 87.63,44.45 C55.+
N$42
  Top 0.254: C48.2 R56.1
N$43  (via drill 0.41)
  Top 0.254: 97.79,11.75 97.79,10.79 97.47,10.48 U5.6 v94.14,10.48 | 97.79,11.75 97.79,16.51 98.11,16.83 R36.2 | 97.79,11.75 U5.7 | R30.2 v78.42,5.71
  Bottom 0.254: v94.14,10.48 88.9,10.48 88.27,11.11 88.27,17.78 87.63,18.41 79.06,18.41 78.42,17.78 v78.42,5.71
N$44
  Top 0.178: U3.28 26.35,15.02 26.35,17.14 C10.1
N$45
  Top 0.178: U3.2 19.6,14.37 19.37,14.6 19.37,15.24 19.05,15.56 16.51,15.56 16.19,15.87 C13.2
N$46
  Top 0.178: U3.24 24.73,12.42 24.13,13.02 C10.2
N$47  (via drill 0.41)
  Top 0.254: C31.1 v107,4.13 | v142.88,2.86 150.5,2.86 152.08,4.44 152.08,29.84 151.13,30.8 R27.2
  Bottom 0.254: v142.88,2.86 107.31,2.86 107,3.17 v107,4.13
N$48
  Top 0.254: U7.2 108.58,22.54 108.27,22.22 R46.1 108.27,15.56 108.58,15.24 109.86,15.24 110.17,14.92 C44.1
N$49
  Top 0.254: R71.3 150.5,7.94 148.27,5.71 139.86,5.71 139.38,5.24 C62.1 139.38,2.86 139.06,2.54 75.25,2.54 74.61,3.17 74.61,13.33 74.93,13.65 C61.2
N$50
  Top 0.254: R71.2 146.69,7.94 146.05,7.3 R72.2
N$52
  Top 0.254: Y3.1 92.39,51.12 92.39,48.26 93.03,47.62 C53.1 R55.2 95.25,43.66 95,43.41 U8.2
N$53
  Top 0.254: Y3.2 100.01,51.12 100.01,48.26 99.38,47.62 C54.1 R55.1 97.16,44.61 95.65,43.1 U8.1
N$54
  Top 0.254: C49.2 R54.2 92.71,30.8 92.4,31.11 U8.19
N$55  (via drill 0.41)
  Top 0.254: U10.7 v124.78,11.75 125.73,11.75 126.05,12.06 R83.1 | v139.38,12.06 R53.2 | v138.11,7.3 R56.2
  Bottom 0.254: v139.38,12.06 138.11,12.06 137.79,11.75 136.84,11.75 | v124.78,11.75 136.84,11.75 | 136.84,11.75 136.84,7.62 137.16,7.3 v138.11,7.3
N$56
  Top 0.254: R43.2 C39.1
N$57  (via drill 0.41)
  Top 0.254: JP4.2 93.34,19.05 92.71,19.68 90.17,19.68 89.53,20.32 R47.2 C46.2 85.09,23.18 84.77,23.49 84.77,26.03 85.09,26.35 87,26.35 87.31,26.67 87.31,31.59 89.15,33.43 U8.14 | v99.38,21.59 R43.1
  Bottom 0.254: v99.38,21.59 93.66,21.59 93.34,21.27 JP4.2
N$58
  Top 0.254: U8.13 88.5,33.57 85.72,30.8 C57.1
N$59
  Top 0.254: 88.11,25.08 88.11,29.53 | C46.1 88.11,25.08 | 88.11,29.53 C41.1 | 88.11,25.08 R47.1 R42.1 | U8.15 89.8,33.28 88.11,31.59 88.11,29.53
N$60  (via drill 0.41)
  Top 0.254: U10.6 R60.2 126.05,9.21 126.36,8.89 130.49,8.89 | 130.49,8.89 v138.11,8.89 | 130.49,8.89 C48.1 | R52.1 148.55,11.11 146.69,11.11 144.46,8.89 v142.88,8.89
  Bottom 0.254: v138.11,8.89 v142.88,8.89
N$61  (via drill 0.41)
  Top 0.254: C58.2 143.83,16.83 145.73,18.73 v145.73,28.57 145.73,31.43 146.69,32.38 146.69,34.61 150.5,38.42 R63.3 150.5,40.96
  Bottom 0.254: R66.3 142.08,29.05 142.56,28.57 v145.73,28.57
N$62  (via drill 0.41)
  Top 0.254: v133.67,10.48 R59.1 | 102.55,23.18 C50.2
  Top 0.406: v102.55,21.59 102.55,23.18
  Bottom 0.254: v102.55,21.59 102.55,18.41 103.19,17.78 112.08,17.78 112.39,17.46 112.39,11.11 113.03,10.48 v133.67,10.48
N$63
  Top 0.254: U1.3 41.91,52.39 42.23,52.07 42.23,50.8 43.18,49.85 44.29,49.85 44.61,49.53 44.61,47.78 45.24,47.15 56.67,47.15 57.15,46.67 57.15,44.13 57.78,43.5 B1.+
N$64
  Top 0.254: C33.1 C32.2 R33.2
N$65
  pour Bottom (no thermals): 65.88,58.9 72.71,58.9 72.71,56.67 65.88,56.67
N$66  (via drill 0.41)
  Top 0.178: R15.2 v60.33,51.43 | Q3.1 105.73,54.61 v103.5,54.61
  Bottom 0.178: v103.5,54.61 102.23,54.61 101.6,55.24 65.41,55.24 64.77,54.61 64.77,53.02 64.45,52.7 60.64,52.7 60.33,52.39 v60.33,51.43
N$67
  Top 0.178: R9.2 41.59,44.13 41.91,44.45 42.86,44.45 43.02,44.61 Q2.1
N$68
  Top 0.61: Q2.2 Q2.4 38.42,46.99 37.47,47.94 X5.2
N$69
  Top 0.813: X5.1 33.02,45.4 32.7,45.08 R6.2
N$70
  Top 0.254: R34.1 80.96,14.92 81.28,15.24 87,15.24 87.31,14.92 R29.2 88.58,13.65 88.9,13.33 88.9,12.06 89.22,11.75 U5.8
N$72
  Top 0.254: U5.9 R39.1 87.31,11.75 87,12.06 82.87,12.06 | 82.87,12.06 R34.2 | C36.2 82.87,12.06
N$73
  Top 0.254: R57.1 94.61,23.18 94.3,23.49 94.3,26.03 93.98,26.35 91.12,26.35 90.81,26.67 90.81,30.96 91.1,31.25 U8.17
N$76  (via drill 0.41)
  Top 0.254: R19.1 66.36,47.94 v66.36,45.08 | v66.36,45.08 D2.C | Q5.1 66.36,43.33 v66.36,45.08
N$77
  Top 0.254: R30.1 C35.1
N$78
  pour Top (isolate 0.61, rank 2, no thermals): 18.41,41.59 12.7,41.59 12.06,42.23 12.06,52.7 12.7,53.34 16.51,53.34 16.51,50.16 14.61,50.16 13.97,49.53 13.97,44.77 14.61,44.13 18.41,44.13
N$79  (via drill 0.41)
  Top 0.178: R17.2 v63.5,51.43
  Top 0.254: v113.98,56.51 118.11,56.51 Q4.1
  Bottom 0.178: v113.98,56.51 113.98,53.97 113.67,53.66 102.23,53.66 101.28,54.61 66.04,54.61 65.72,54.29 65.72,51.75 65.41,51.43 v63.5,51.43
N$80
  Top 0.254: R58.1 100.33,23.18 100.65,23.49 100.65,26.03 100.33,26.35 97.79,26.35 97.47,26.67 97.47,30.48 97.16,30.8 94.46,30.8 94.14,31.11 94.14,32.7 93.7,33.14 U8.21
N$81
  pour Top (isolate 0.61, no thermals): 14.92,63.5 17.14,63.5 17.78,62.86 17.78,59.05 16.51,57.78 12.7,57.78 12.7,60.64 13.97,61.91 13.97,66.83 13.97,66.99 13.34,67.63 12.7,67.63 12.7,69.53 14.61,69.53 14.61,66.83 14.61,63.82
N$82
  Top 0.254: 99.38,8.89 98.42,8.89 98.11,9.21 U5.5 | 99.38,8.89 C34.2 | 99.38,8.89 100.97,8.89 101.28,8.57 R24.2
N$83
  Top 0.254: R52.2 148,14.01 147.64,13.65 R53.1
  Bottom 0.254: R52.2 148,17.5 148.55,18.06 R52.3
N$84
  Top 0.254: U9.14 103.5,49.21 103.98,49.69 C67.+
N$85
  Top 0.254: U10.9 116.2,10.48 115.89,10.16 115.89,9.21 115.57,8.89 112.71,8.89 | 110.17,8.89 112.71,8.89 | 110.17,8.89 R48.2 | 112.71,8.89 R44.1 | 110.17,8.89 108.58,8.89 108.27,9.21 C42.1
N$86  (via drill 0.41, 0.61)
  Top 0.61: U12.3 | U12.3 | U12.3 38.26,19.37 v36.83,19.37 C79.+
  SUPPLY 0.406: v36.83,19.37 55.56,19.37 56.2,18.73 v64.77,18.73
  pour Top (no thermals): 62.71,21.59 64.29,21.59 64.61,21.91 66.83,21.91 66.83,16.19 64.45,16.19 64.14,16.51 64.14,20 63.82,20.32 62.71,20.32
N$87
  Top 0.254: 114.62,12.06 R44.2 | 114.62,12.06 115.89,12.06 116.2,11.75 117.16,11.75 | 117.16,11.75 U10.8 | C42.2 110.17,11.75 110.49,12.06 114.62,12.06 | 117.16,11.75 R82.1
N$88
  Top 0.254: C34.1 101.28,11.75 100.97,12.06 99.69,12.06 99.38,12.38 C33.2 99.38,14.92 99.69,15.24 100.97,15.24 101.28,15.56 R36.1
N$89
  Top 0.254: R58.2 R57.2 C49.1 R54.1 91.6,27.62 91.44,27.78 91.44,30.8 91.75,31.11 U8.18
N$90  (via drill 0.41)
  Top 0.406: v8.26,51.12 D11.K
  Top 0.61: Q1.3 | v14.92,29.69 Q1.3
  Bottom 0.406: v8.26,51.12 8.26,40.96 13.65,35.56 13.65,30.16 14.13,29.69 v14.92,29.69
N$91  (via drill 0.41)
  Top 0.406: v8.26,52.7 2.06,52.7 1.75,52.39 D11.A
  Top 0.61: v14.76,33.65 R7.2
  Bottom 0.406: v8.26,52.7 9.21,51.75 9.21,41.27 14.76,35.72 v14.76,33.65
N$92
  Top 0.178: R8.2 29.69,33.18 27.94,34.92 24.45,34.92 24.13,34.61 24.13,29.21 23.66,28.74 Q1.1
N$93
  Top 0.254: C47.2 R51.1
N$94  (via drill 0.41)
  Top 0.254: v102.55,7.3 C29.2 R25.2 103.82,11.75 104.14,12.06 105.41,12.06 105.73,12.38 C32.1 | U5.1 v97.79,4.13
  Bottom 0.254: v102.55,7.3 102.55,4.44 102.23,4.13 v97.79,4.13
N$95
  Top 0.254: U5.10 89.22,9.21 88.9,8.89 80.96,8.89 | 80.96,8.89 C36.1 | R38.1 76.52,9.21 76.83,8.89 78.42,8.89 | C35.2 78.42,8.89 | 78.42,8.89 80.96,8.89
N$96  (via drill 0.41)
  Top 0.254: C37.1 v84.14,7.3 C38.2 85.41,6.35 85.72,6.03 88.58,6.03 89.22,6.67 U5.12 | v84.14,13.65 R29.1
  Bottom 0.254: v84.14,13.65 83.5,13.65 83.19,13.33 83.19,7.62 83.5,7.3 v84.14,7.3
N$98
  Top 0.254: R25.1 C29.1 105.73,6.03 105.41,5.71 99.38,5.71 | 99.38,5.71 98.11,5.71 97.79,5.4 U5.2 | 99.38,5.71 R28.2
N$99
  Top 0.254: R28.1 C31.2
N$102
  Top 0.254: 82.87,5.4 R40.1 | 82.87,5.4 85.41,5.4 | 85.41,5.4 U5.13 | 82.87,5.4 81.28,5.4 80.96,5.71 C37.2 | 85.41,5.4 R35.2
N$105  (via drill 0.41)
  Top 0.178: R1.1 v51.75,10
  Bottom 0.178: JP2.1 45.09,5.4 44.77,5.71 44.77,9.52 45.24,10 v51.75,10
N$106
  Top 0.254: R60.1 C51.2
N$107
  Top 0.178: R4.1 54.29,9.84 | JP2.3 50.48,6.67 53.98,6.67 54.29,6.98 54.29,9.84 | 54.29,9.84
N$108
  Top 0.178: R3.1 JP2.4
N$109
  Top 0.254: 127.95,5.71 125.41,5.71 124.46,6.67 U10.3 | 127.95,5.71 130.49,5.71 | 127.95,5.71 R78.2 | 130.49,5.71 R74.1 | C66.1 135.25,4.13 135.25,5.4 134.94,5.71 130.49,5.71
N$111  (via drill 0.41)
  Top 0.254: U5.14 v88.58,4.13 R35.1 | v79.69,16.83 R31.2
  Bottom 0.254: v79.69,16.83 86.04,16.83 86.68,16.19 86.68,4.76 R35.1 v88.58,4.13
PA0
  Top 0.178: 26.19,37.94 29.53,34.61 38.73,34.61 | J1.7 | 26.19,37.94 | 26.19,37.94 J1.7 | U2.51 40.05,32.02 39.69,32.38 39.69,34.29 39.37,34.61 38.73,34.61 | 38.73,34.61
PA1
  Top 0.178: J1.8 | J1.8 24.13,40 26.51,40 26.83,39.69 26.83,37.94 29.69,35.08 39.21,35.08 | U2.50 40.52,32.82 40.32,33.02 40.32,34.61 39.85,35.08 39.21,35.08 | 39.21,35.08
PA2
  Top 0.178: J1.9 | J1.9 26.99,41.27 27.3,40.96 27.3,38.1 29.84,35.56 40.32,35.56 41.41,34.47 U2.49
PA3
  Top 0.178: J1.10 | J1.10 24.13,42.54 27.46,42.54 27.78,42.23 27.78,38.26 30,36.04 42.07,36.04 42.68,35.42 U2.48
PA4
  Top 0.178: J1.11 27.94,43.81 28.26,43.5 28.26,38.42 30.16,36.51 43.81,36.51 44.01,36.31 U2.47
PA5
  Top 0.178: J1.12 | J1.12 24.13,45.08 28.42,45.08 28.73,44.77 28.73,38.58 30.32,36.99 44.45,36.99 44.81,36.63 U2.46
PA6
  Top 0.178: J1.13 | J1.13 28.73,46.35 29.21,45.88 29.21,38.73 30.48,37.46 44.93,37.46 45.61,36.78 U2.45
PA7
  Top 0.178: J1.14 | J1.14 22.86,47.31 23.18,47.62 29.37,47.62 29.69,47.31 29.69,38.89 30.64,37.94 45.4,37.94 46.41,36.93 U2.44
PTT
  Bottom 0.61: X3.1 X4.1
  pour Top (isolate 0.61, rank 3, no thermals): 102.87,60.96 102.87,75.25 143.19,75.25 143.19,70.8 140.65,70.8 140.65,72.07 140.02,72.71 114.62,72.71 113.98,72.07 113.98,60.96
PTT_DRIVE  (via drill 0.41)
  Top 0.178: v60.33,46.35 R15.1 | U2.36 52.81,41.06 53.98,42.23 v53.98,43.5
  Bottom 0.178: v53.98,43.5 55.88,43.5 56.2,43.81 56.2,46.04 56.52,46.35 v60.33,46.35
RESET
  Top 0.178: JP1.6 62.55,9.37 62.23,9.68 57.31,9.68 | 57.31,9.68 55.56,9.68 55.24,9.37 55.24,5.71 54.93,5.4 JP2.5 | C5.1 57.31,9.68 | U2.20 58.21,24.02 58.42,23.81 58.42,20 57.31,18.89 R5.1 57.31,14.6 | C5.1 57.15,11.11 57.16,11.12 | 57.31,14.6 D1.A | 57.31,14.6 C5.1
RX_AUDIO_OUT  (via drill 0.41)
  Top 0.254: v90.17,31.75 90.17,32.86 90.45,33.14 U8.16 | v93.34,31.75 93.34,32.54 93.05,32.84 U8.20 | v82.55,42.86 82.55,44.13 81.92,44.77 81.92,52.07 81.6,52.39 C43.1 TP6.TP
  Bottom 0.254: 90.17,34.29 93.34,34.29 | 90.17,34.29 85.41,34.29 85.09,34.61 85.09,42.54 84.77,42.86 v82.55,42.86 | 90.17,34.29 v90.17,31.75 | 93.34,34.29 v93.34,31.75 | 93.34,34.29 106.68,34.29 107.31,33.65 117.79,33.65 119.06,32.38 119.06,29.21 119.7,28.57 126.05,28.57 J2.1
RX_AUDIO_RET  (via drill 0.41)
  Top 0.254: U7.5 v119.06,20
  Bottom 0.254: v119.06,20 119.06,26.67 119.7,27.3 J2.2
SPI_MISO  (via drill 0.41)
  Top 0.178: v56.2,39.37 92.39,39.37 92.55,39.53 v93.03,40 93.03,41.52 U8.5 | v97.95,40 116.84,40 117.47,40.64 U9.3 v117.47,44.45 | v51.59,33.18 51.59,22.38 52.81,21.16 U2.13
  Bottom 0.178: v93.03,40 v97.95,40 | v56.2,39.37 53.18,39.37 52.7,38.89 52.7,33.5 52.39,33.18 v51.59,33.18 | J2.14 123.19,42.54 122.87,42.86 118.11,42.86 117.47,43.5 v117.47,44.45
SPI_MOSI  (via drill 0.41)
  Top 0.178: 57.31,38.89 92.87,38.89 93.19,39.21 v94.14,39.21 94.14,40.16 93.7,40.6 U8.4 | v96.84,39.21 99.06,39.21 99.38,39.53 118.27,39.53 118.75,40 v118.75,40.96 U9.2 | 57.31,38.89 | v56.83,38.42 57.31,38.89 | U2.12 52.01,21.01 50.8,22.22 v50.8,31.75
  Bottom 0.178: v94.14,39.21 v96.84,39.21 | v56.83,38.42 53.66,38.42 53.34,38.1 53.34,32.7 53.02,32.38 52.07,32.38 51.44,31.75 v50.8,31.75 | v118.75,40.96 122.24,40.96 123.19,40 J2.12
SPI_SCK  (via drill 0.41)
  Top 0.178: 95.09,38.42 58.74,38.42 v56.52,36.19 | 95.09,38.42 99.06,38.42 99.69,39.05 v120.33,39.05 | v120.33,36.51 120.33,35.24 120.02,34.92 U9.28 | v50.01,30.64 50.01,22.07 51.21,20.86 U2.11 51.21,17.37 51.59,16.99 51.59,15.72 52.07,15.24 53.98,15.24 54.29,14.92 R4.2 | U8.3 94.35,40.59 95.09,39.85 95.09,38.42
  Bottom 0.178: v120.33,39.05 120.33,37.46 | v50.01,30.64 51.28,30.64 52.23,31.59 56.04,31.59 56.52,32.07 v56.52,36.19 | 120.33,37.46 v120.33,36.51 | 120.33,37.46 J2.10
SPI_SS  (via drill 0.41)
  Top 0.178: U2.33 55.21,39.97 56.2,40.96 56.2,46.04 55.88,46.35 v53.02,46.35
  Bottom 0.178: J2.16 123.03,45.08 122.08,46.04 119.38,46.04 117.47,47.94 117.47,60.64 115.25,62.86 60.01,62.86 53.34,56.2 53.34,47.47 53.02,47.15 v53.02,46.35
SS_ISD  (via drill 0.41)
  Top 0.178: v52.39,30.64 52.39,23.65 55.21,20.83 U2.16 | v57.78,36.19 59.53,37.94 99.38,37.94 100.01,38.58 118.9,38.58 119.22,38.26 120.97,38.26 121.28,38.58 121.28,42.23 120.81,42.7 U9.1 | U9.1 120.02,42.54 | U9.1
  Bottom 0.178: v57.78,36.19 57.78,31.43 56.99,30.64 v52.39,30.64
SS_MX828  (via drill 0.41)
  Top 0.178: 57.31,39.85 | v50.16,33.18 49.53,33.18 49.21,32.86 49.21,21.91 50.41,20.71 U2.10 | v56.83,40.32 57.31,39.85 | U8.6 92.4,40.33 91.92,39.85 57.31,39.85
  Bottom 0.178: v56.83,40.32 52.7,40.32 52.07,39.69 52.07,34.45 51.75,34.13 51.12,34.13 v50.16,33.18
TCK
  Top 0.178: JP1.1 57.47,4.29 57.15,3.97 45.4,3.97 44.77,4.6 44.77,13.97 44.13,14.6 RN1.1 41.91,16.99 41.12,17.78 31.27,17.78 30.96,18.1 30.96,27.94 31.27,28.26 39.37,28.26 40.41,27.22 U2.57
TDI
  Top 0.178: JP1.9 67.63,3.02 67.15,2.54 44.77,2.54 43.18,4.13 43.18,9.52 42.86,9.84 34.61,9.84 | U2.54 41.41,29.69 30.64,29.69 29.53,28.57 29.53,17.14 30.32,16.35 34.29,16.35 34.61,16.03 34.61,14.6 | 34.61,14.6 RN1.4 | 34.61,14.6 34.61,9.84 | R12.1 34.61,7.94 34.61,9.84
TDO  (via drill 0.41)
  Top 0.178: JP1.3 60.01,3.81 59.21,3.02 45.09,3.02 43.81,4.29 43.81,12.38 43.5,12.7 39.37,12.7 | U2.55 40.55,28.82 40.16,29.21 30.8,29.21 30,28.42 30,17.46 30.64,16.83 39.05,16.83 39.37,16.51 RN1.3 39.37,12.7 | 39.37,12.7 36.51,12.7 36.2,12.38 v36.2,11.43
  Top 0.254: v34.29,6.35 R14.1
  Bottom 0.178: v34.29,6.35 34.29,11.11 34.61,11.43 v36.2,11.43
TMS
  Top 0.178: JP1.5 62.55,6.35 62.23,6.67 59.21,6.67 58.74,6.19 58.74,3.97 58.26,3.49 45.24,3.49 44.29,4.44 44.29,12.7 43.66,13.33 40.96,13.33 40.64,13.65 RN1.2 40.64,16.67 40.01,17.3 30.96,17.3 30.48,17.78 30.48,28.26 30.96,28.73 39.85,28.73 40.56,28.02 U2.56
TX_AUDIO  (via drill 0.41)
  Top 0.254: X3.7 144.46,55.88 145.1,55.24 145.1,49.21 143.83,47.94 v143.83,40.32 v143.83,20 | C52.2 v133.67,13.65 | v141.92,40.32 R61.2
  Bottom 0.254: v133.67,13.65 134.62,14.6 142.88,14.6 143.83,15.56 v143.83,20 | J2.5 129.86,32.38 137.79,40.32 v141.92,40.32 v143.83,40.32
  Bottom 0.61: X3.7 X4.7
TX_TONE_OUT  (via drill 0.41)
  Top 0.254: 104.78,24.76 102.55,24.76 C50.1 | v105.73,24.76 104.78,24.76 | 104.78,24.76 TP5.TP | U8.23 95,33.59 v95.73,32.86
  Bottom 0.254: v95.73,32.86 95.73,25.4 96.36,24.76 v105.73,24.76
VBATT  (via drill 0.41)
  Top 0.178: v45.56,48.1 56.36,48.1 56.83,48.58 D7.C | U2.59 42.61,25.62 42.86,25.88 v42.86,26.99
  Top 0.406: R23.2 C20.1 R21.1 59.05,53.02 58.1,52.07 D7.C
  Bottom 0.178: v42.86,26.99 41.91,26.99 41.59,27.3 41.59,33.34 41.91,33.65 42.86,33.65 43.5,34.29 43.5,47.47 44.13,48.1 v45.56,48.1
VEE_LCD
  Top 0.254: J1.3 27.94,33.65 28.89,32.7 28.89,16.83 30.16,15.56 33.02,15.56 33.66,14.92 33.66,10.16 33.02,9.52 30.8,9.52 30.48,9.21 R2.2
VREF  (via drill 0.41)
  Top 0.254: 119.7,9.21 U10.10 | 119.7,9.21 U10.5 | U10.14 U10.13 v119.7,5.4 119.7,9.21 | R24.1 98.42,7.3 v97.79,6.67 U5.3
  Bottom 0.254: v119.7,5.4 110.81,5.4 110.17,6.03 110.17,8.89 109.54,9.52 98.42,9.52 97.79,8.89 v97.79,6.67
VSQL  (via drill 0.41)
  Top 0.178: U2.61 41.41,23.97 v44.77,23.97
  Top 0.254: R37.1 R31.1 82.55,16.83 82.55,18.57 | 82.55,18.57 82.55,20.48 | v87.31,35.56 84.61,35.56 83.34,34.29 83.34,24.45 82.55,23.65 82.55,22.86 | 82.55,18.57 v76.52,18.57 76.52,20.48 C78.+ 75.56,20.48 | 82.55,22.86 TP3.TP | 82.55,20.48 D10.C | 82.55,20.48 82.55,22.86 | U8.9 90.45,42.82 v91.12,43.5
  Bottom 0.178: v44.77,23.97 45.4,23.34 45.4,20.16 45.72,19.84 53.66,19.84 54.45,19.05 54.45,15.08 55.24,14.29 75.88,14.29 76.52,14.92 v76.52,18.57
  Bottom 0.254: v87.31,35.56 87.31,36.83 91.12,40.64 v91.12,43.5
VTEMP  (via drill 0.41)
  Top 0.178: v43.66,24.76 | U2.60 41.41,24.76 v43.66,24.76
  Top 0.254: R20.1 v65.72,11.11 C19.1 | C19.1 | C19.1 66.99,13.65 R22.2
  Bottom 0.178: v43.66,24.76 43.66,23.81 44.45,23.02 44.77,22.7 44.77,20 45.4,19.37 53.5,19.37 53.98,18.89 53.98,14.92 55.24,13.65 65.09,13.65 65.72,13.02 v65.72,11.11
XADC  (via drill 0.41)
  Top 0.178: U2.58 41.41,26.51 v40.01,26.51
  Bottom 0.178: v40.01,26.51 40.01,33.65 40.64,34.29 42.55,34.29 42.86,34.61 42.86,54.29 45.09,56.51 49.85,56.51 58.74,65.41 116.52,65.41 120.02,61.91 120.02,50.48 120.33,50.16 J2.20

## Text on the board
GROUND: KG4LNE
SUPPLY: KG4LNE
Bottom: MICRO-RC | 3XX-100 | TP8 | MADE IN USA
tPlace: 1 | PTT | DGND | AGND | FAN | COS | GND | AGND | 12V | RX | 5V | TX | AUX | 8 | CPU | 3V | BKLITE | INPUT | LVL | LCD | PWR | MADE IN USA | EXPANSION I/O | RECEIVE | LVL | MICRO-RC | REV- | RECORD | LVL | SQUELCH | CAL | EMPH | FLAT | PLAY | LVL | OUTPUT | LVL | BEEP | LVL | 1 | 2 | ISP | JTAG | RS232 | CONTRAST
bRestrict: 12VDC | - | +
Document: FABRICATION DRAWING | DRILL PLAN | SYM | SIZE | TOL. | CNT | PLATE | 0.016 in | +/-0.003 in | 241 | Yes | 0.024 in | +/-0.003 in | 31 | Yes | 0.032 in | +/-0.003 in | 14 | Yes | 0.036 in | +/-0.003 in | 21 | Yes | 0.040 in | +/-0.003 in | 69 | Yes | 0.043 in | +/-0.003 in | 8 | Yes | 0.050 in | +/-0.003 in | 8 | Yes | 0.056 in | +/-0.003 in | 2 | Yes | 0.070 in | +/-0.003 in | 3 | Yes | 0.120 in | +/-0.003 in | 6 | 2 | TOTAL | 403 | 399 | NOTES: | 1. PRINTED CIRCUIT BOARD MADE FROM NEMA GRADE FR-4 EPOXY LAMINATE | WITH 1 OUNCE COPPER PLATING AND .062 THICKNESS. | 2. ALL DIMENSIONS ARE GIVEN IN INCHES. | 3. CIRCUIT PATHS ARE FOR REFERENCE ONLY. | 4. HOLE SIZES SHOWN ARE FINISHED DIAMETERS AFTER PLATING. | 5. BOARD PLATED USING REFLOW OR SIMILAR METHOD. | 6. BOARD TO HAVE GREEN SOLDER MASK ON PLATED SURFACES USING WET FILM | SR100 OR SR1010 EPOXY. EQUIVALENT WET OR DRY FILM MAY BE USED. | 7. SILKSCREEN BOARD USING WHITE INK. | 8. THE FOLLOWING INFORMATION APPLIES TO THIS BOARD: | * 4 COPPER LAYERS | RES | * .062 BOARD THICKNESS | MICRO-RC CONTROLLER | C | * REQUIRES TOP SIDE SILKSCREEN | KO | MD-3XX-01 | 01/09/09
